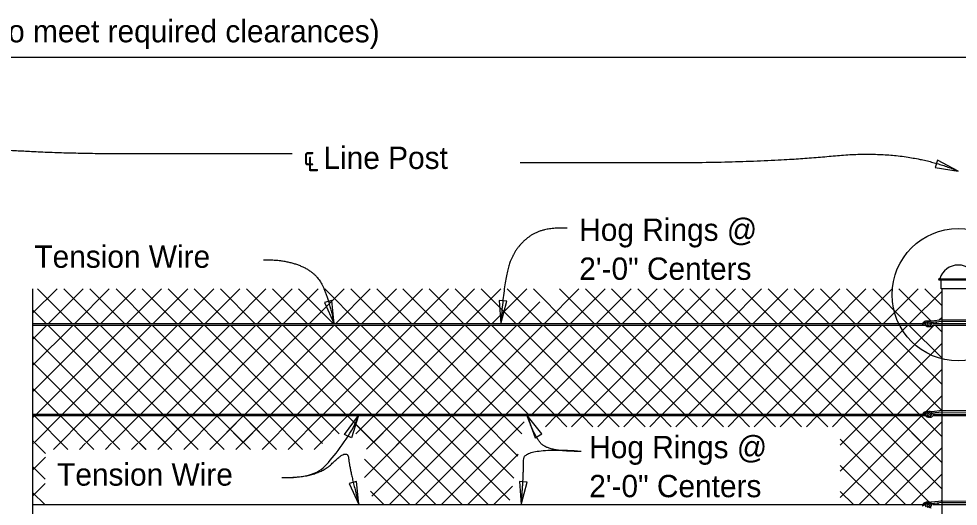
# Model space of a CAD drawing. Extents: x 0 to 41, y -96 to 25.
# Drawn here: x 16.84 to 25.32, y 20.56 to 24.96 of the extents above; entities that cross this region are included whole.
import ezdxf

# ---------------------------------------------------------------- set-up
doc = ezdxf.new("R2010")
doc.units = 0
for name, color, linetype in [('Dimension', 7, 'Continuous'), ('Miscellaneous', 7, 'Continuous'), ('SteelMisc', 7, 'Continuous'), ('SteelMisc_h', 7, 'Continuous'), ('TextStructures', 7, 'Continuous')]:
    doc.layers.add(name, color=color, linetype=linetype)

msp = doc.modelspace()

# ---------------------------------------------------------------- linework, layer by layer
at = {"layer": 'Dimension'}
for points in [[(14.3237, 24.6092), (15.7874, 24.6092), (15.7874, 24.7126), (15.8324, 24.6092), (15.8774, 24.5059), (15.8774, 24.6092), (29.1682, 24.6092)], [(16.9607, 22.5181), (16.9607, 19.3509), (17.064, 19.3509), (16.9607, 19.3059), (16.8574, 19.2609), (16.9607, 19.2609), (16.9607, 18.3673)]]:
    msp.add_lwpolyline(points, dxfattribs=at)
for points in [[(25.3238, 23.582), (25.1374, 23.6813), (25.1151, 23.6144)], [(19.6851, 22.2037), (19.6649, 22.414), (19.5967, 22.3956)], [(21.1903, 22.2037), (21.2464, 22.4074), (21.1762, 22.4145)], [(19.9044, 21.3734), (19.8413, 21.1718), (19.7784, 21.2039)], [(21.4293, 21.3734), (21.5009, 21.1747), (21.5624, 21.2094)], [(19.9087, 20.57), (19.8885, 20.7803), (19.8203, 20.7619)], [(21.3736, 20.5698), (21.4296, 20.7734), (21.3594, 20.7805)]]:
    msp.add_lwpolyline(points, close=True, dxfattribs=at)
msp.add_circle((25.3237, 22.4656), 0.5976, dxfattribs=at)
for points, degree in [([(19.3053, 23.7363), (18.502, 23.7363), (17.1126, 23.7363), (15.9312, 23.8309), (15.3237, 23.935)], 2), ([(21.3649, 23.6582), (21.8115, 23.6582), (23.579, 23.6582), (24.8456, 23.7812), (25.3237, 23.5819)], 2), ([(21.79, 23.0656), (21.5721, 23.0781), (21.3283, 22.9036), (21.2222, 22.6197), (21.1904, 22.2037)], 2), ([(19.0466, 22.7791), (19.227, 22.7862), (19.51, 22.6764), (19.6303, 22.4569), (19.6851, 22.2037)], 2), ([(19.2125, 20.8146), (19.5006, 20.8172), (19.62, 20.9127), (19.8603, 21.2414), (19.904, 21.3726)], 3), ([(21.9165, 21.0507), (21.6205, 21.0483), (21.4904, 21.1931), (21.4293, 21.3734)], 2), ([(21.9165, 21.0507), (21.3904, 21.0866), (21.3958, 20.8597), (21.3736, 20.5697)], 2), ([(19.2125, 20.8146), (19.5352, 20.808), (19.8072, 21.083), (19.8238, 20.8929), (19.9086, 20.57)], 2)]:
    msp.add_open_spline(points, degree=degree, dxfattribs=at)
at = {"layer": 'Miscellaneous'}
for p, q in [((16.9607, 22.2978), (17.181, 22.5181)), ((17.0061, 22.5181), (17.3187, 22.2055)), ((17.1046, 22.2055), (17.4171, 22.5181)), ((17.2423, 22.5181), (17.5548, 22.2055)), ((17.3408, 22.2055), (17.6533, 22.5181)), ((17.4785, 22.5181), (17.791, 22.2055)), ((17.577, 22.2055), (17.8895, 22.5181)), ((17.7142, 22.5181), (18.0267, 22.2055)), ((17.8131, 22.2055), (18.1257, 22.5181)), ((17.9499, 22.5181), (18.2624, 22.2055)), ((18.0493, 22.2055), (18.3618, 22.5181)), ((18.1856, 22.5181), (18.4981, 22.2055)), ((18.285, 22.2055), (18.5975, 22.5181)), ((18.4213, 22.5181), (18.7338, 22.2055)), ((18.5207, 22.2055), (18.8332, 22.5181)), ((18.657, 22.5181), (18.9695, 22.2055)), ((18.7564, 22.2055), (19.0689, 22.5181)), ((18.8927, 22.5181), (19.2052, 22.2055)), ((18.9921, 22.2055), (19.3047, 22.5181)), ((19.1284, 22.5181), (19.4409, 22.2055)), ((19.2278, 22.2055), (19.5404, 22.5181)), ((19.3641, 22.5181), (19.6766, 22.2055)), ((19.4635, 22.2055), (19.7761, 22.5181)), ((19.5998, 22.5181), (19.9123, 22.2055)), ((19.6992, 22.2055), (20.0118, 22.5181)), ((19.8355, 22.5181), (20.148, 22.2055)), ((19.9349, 22.2055), (20.2475, 22.5181)), ((20.0712, 22.5181), (20.3837, 22.2055)), ((20.1706, 22.2055), (20.4832, 22.5181)), ((20.3069, 22.5181), (20.6194, 22.2055)), ((20.4063, 22.2055), (20.7189, 22.5181)), ((20.5426, 22.5181), (20.8551, 22.2055)), ((20.642, 22.2055), (20.9546, 22.5181)), ((20.7783, 22.5181), (21.0908, 22.2055)), ((20.8777, 22.2055), (21.1903, 22.5181)), ((21.014, 22.5181), (21.3265, 22.2055)), ((21.1134, 22.2055), (21.426, 22.5181)), ((21.2497, 22.5181), (21.5622, 22.2055)), ((21.4854, 22.5181), (21.7979, 22.2055)), ((21.5848, 22.2055), (21.8974, 22.5181)), ((21.7211, 22.5181), (22.0336, 22.2055)), ((21.8205, 22.2055), (22.1331, 22.5181)), ((21.9568, 22.5181), (22.2693, 22.2055)), ((22.0562, 22.2055), (22.3688, 22.5181)), ((22.1925, 22.5181), (22.505, 22.2055)), ((22.2919, 22.2055), (22.6045, 22.5181)), ((22.4282, 22.5181), (22.7407, 22.2055)), ((22.5276, 22.2055), (22.8402, 22.5181)), ((22.6639, 22.5181), (22.9765, 22.2055)), ((22.7634, 22.2055), (23.0759, 22.5181)), ((22.8996, 22.5181), (23.2122, 22.2055)), ((22.9991, 22.2055), (23.3116, 22.5181)), ((23.1353, 22.5181), (23.4479, 22.2055)), ((23.2348, 22.2055), (23.5473, 22.5181)), ((23.371, 22.5181), (23.6836, 22.2055)), ((23.4705, 22.2055), (23.783, 22.5181)), ((23.6067, 22.5181), (23.9193, 22.2055)), ((23.7062, 22.2055), (24.0187, 22.5181)), ((23.8424, 22.5181), (24.155, 22.2055)), ((23.9419, 22.2055), (24.2544, 22.5181)), ((24.0786, 22.5181), (24.3911, 22.2055)), ((24.1776, 22.2055), (24.4901, 22.5181)), ((24.3148, 22.5181), (24.6273, 22.2055)), ((24.4133, 22.2055), (24.7258, 22.5181)), ((24.5509, 22.5181), (24.8635, 22.2055)), ((24.649, 22.2055), (24.9615, 22.5181)), ((24.7871, 22.5181), (25.0782, 22.227)), ((24.8847, 22.2055), (25.1779, 22.4988)), ((25.0233, 22.5181), (25.1779, 22.3635)), ((16.9607, 22.3273), (17.0825, 22.2055)), ((21.3496, 22.2055), (21.5441, 22.4)), ((25.1494, 22.2346), (25.1779, 22.2631)), ((16.9607, 21.5893), (17.5622, 22.1908)), ((16.9607, 21.8254), (17.326, 22.1908)), ((16.9607, 22.0616), (17.0899, 22.1908)), ((16.9957, 21.3881), (17.7984, 22.1908)), ((17.0972, 22.1908), (17.8999, 21.3881)), ((17.2319, 21.3881), (18.0346, 22.1908)), ((17.3334, 22.1908), (18.1361, 21.3881)), ((17.4676, 21.3881), (18.2703, 22.1908)), ((17.5696, 22.1908), (18.3722, 21.3881)), ((17.7033, 21.3881), (18.506, 22.1908)), ((17.8058, 22.1908), (18.6084, 21.3881)), ((17.939, 21.3881), (18.7417, 22.1908)), ((18.0415, 22.1908), (18.8441, 21.3881)), ((18.1747, 21.3881), (18.9774, 22.1908)), ((18.2772, 22.1908), (19.0798, 21.3881)), ((18.4104, 21.3881), (19.2131, 22.1908)), ((18.5129, 22.1908), (19.3155, 21.3881)), ((18.6461, 21.3881), (19.4488, 22.1908)), ((18.7486, 22.1908), (19.5512, 21.3881)), ((18.8818, 21.3881), (19.6845, 22.1908)), ((18.9843, 22.1908), (19.7869, 21.3881)), ((19.1175, 21.3881), (19.9202, 22.1908)), ((19.22, 22.1908), (20.0226, 21.3881)), ((19.3532, 21.3881), (20.1559, 22.1908)), ((19.4557, 22.1908), (20.2583, 21.3881)), ((19.5889, 21.3881), (20.3916, 22.1908)), ((19.6914, 22.1908), (20.494, 21.3881)), ((19.8246, 21.3881), (20.6273, 22.1908)), ((19.9271, 22.1908), (20.7297, 21.3881)), ((20.0603, 21.3881), (20.863, 22.1908)), ((20.1628, 22.1908), (20.9654, 21.3881)), ((20.296, 21.3881), (21.0987, 22.1908)), ((20.3985, 22.1908), (21.2011, 21.3881)), ((20.5322, 21.3881), (21.3349, 22.1908)), ((20.6342, 22.1908), (21.4368, 21.3881)), ((20.7674, 21.3881), (21.5701, 22.1908)), ((20.8699, 22.1908), (21.6725, 21.3881)), ((21.0031, 21.3881), (21.8058, 22.1908)), ((21.1056, 22.1908), (21.9082, 21.3881)), ((21.2388, 21.3881), (22.0415, 22.1908)), ((21.3413, 22.1908), (22.1439, 21.3881)), ((21.4745, 21.3881), (22.2772, 22.1908)), ((21.577, 22.1908), (22.3796, 21.3881)), ((21.7103, 21.3881), (22.5129, 22.1908)), ((21.8127, 22.1908), (22.6153, 21.3881)), ((21.946, 21.3881), (22.7486, 22.1908)), ((22.0484, 22.1908), (22.851, 21.3881)), ((22.1817, 21.3881), (22.9843, 22.1908)), ((22.2841, 22.1908), (23.0867, 21.3881)), ((22.4174, 21.3881), (23.22, 22.1908)), ((22.5198, 22.1908), (23.3224, 21.3881)), ((22.6531, 21.3881), (23.4557, 22.1908)), ((22.7555, 22.1908), (23.5581, 21.3881)), ((22.8888, 21.3881), (23.6914, 22.1908)), ((22.9912, 22.1908), (23.7938, 21.3881)), ((23.1245, 21.3881), (23.9271, 22.1908)), ((23.2269, 22.1908), (24.0296, 21.3881)), ((23.3602, 21.3881), (24.1628, 22.1908)), ((23.4626, 22.1908), (24.2653, 21.3881)), ((23.5959, 21.3881), (24.3985, 22.1908)), ((23.6983, 22.1908), (24.501, 21.3881)), ((23.8316, 21.3881), (24.6342, 22.1908)), ((23.934, 22.1908), (24.7367, 21.3881)), ((24.0673, 21.3881), (24.8699, 22.1908)), ((24.1697, 22.1908), (24.9724, 21.3881)), ((24.303, 21.3881), (25.1056, 22.1908)), ((24.4059, 22.1908), (25.1762, 21.4205)), ((24.6421, 22.1908), (25.1779, 21.6549)), ((24.8782, 22.1908), (25.1779, 21.8911)), ((25.0931, 22.2121), (25.0997, 22.2055)), ((25.1144, 22.1908), (25.1779, 22.1273)), ((25.1204, 22.2055), (25.1339, 22.2191)), ((16.9607, 22.0911), (17.6637, 21.3881)), ((24.5387, 21.3881), (25.1779, 22.0274)), ((16.9607, 21.8573), (17.4299, 21.3881)), ((24.7744, 21.3881), (25.1779, 21.7917)), ((16.9607, 21.6216), (17.1942, 21.3881)), ((25.0311, 21.4092), (25.1779, 21.556)), ((16.9607, 21.3531), (16.981, 21.3734)), ((16.9732, 21.3734), (17.2782, 21.0685)), ((16.9823, 21.1385), (17.2172, 21.3734)), ((17.1479, 21.0685), (17.4529, 21.3734)), ((17.2089, 21.3734), (17.5139, 21.0685)), ((17.4446, 21.3734), (17.7496, 21.0685)), ((17.4537, 21.1385), (17.6886, 21.3734)), ((17.6785, 21.3734), (17.9834, 21.0685)), ((17.6894, 21.1385), (17.9243, 21.3734)), ((17.9146, 21.3734), (18.2196, 21.0685)), ((17.9251, 21.1385), (18.16, 21.3734)), ((17.9843, 21.3051), (18.1509, 21.1385)), ((18.0907, 21.0685), (18.3957, 21.3734)), ((18.1508, 21.3734), (18.4557, 21.0685)), ((18.1608, 21.1385), (18.3274, 21.3051)), ((18.22, 21.3051), (18.3867, 21.1385)), ((18.3264, 21.0685), (18.6314, 21.3734)), ((18.387, 21.3734), (18.6919, 21.0685)), ((18.3965, 21.1385), (18.5631, 21.3051)), ((18.4557, 21.3051), (18.6224, 21.1385)), ((18.5622, 21.0685), (18.8671, 21.3734)), ((18.6231, 21.3734), (18.9281, 21.0685)), ((18.6322, 21.1385), (18.7988, 21.3051)), ((18.6914, 21.3051), (18.8581, 21.1385)), ((18.7979, 21.0685), (19.1028, 21.3734)), ((18.8589, 21.3734), (19.1638, 21.0685)), ((18.8679, 21.1385), (19.0345, 21.3051)), ((18.9271, 21.3051), (19.0938, 21.1385)), ((19.0336, 21.0685), (19.3385, 21.3734)), ((19.0946, 21.3734), (19.3995, 21.0685)), ((19.1036, 21.1385), (19.2702, 21.3051)), ((19.1628, 21.3051), (19.3295, 21.1385)), ((19.2693, 21.0685), (19.5742, 21.3734)), ((19.3303, 21.3734), (19.5808, 21.1228)), ((19.3393, 21.1385), (19.5059, 21.3051)), ((19.3985, 21.3051), (19.5652, 21.1385)), ((19.505, 21.0685), (19.8099, 21.3734)), ((19.566, 21.3734), (19.7305, 21.2089)), ((19.8017, 21.3734), (20.6051, 20.57)), ((19.8699, 21.3051), (20.0366, 21.1385)), ((19.8814, 21.2092), (19.9773, 21.3051)), ((19.8849, 21.2127), (20.0456, 21.3734)), ((19.9699, 20.8258), (20.5175, 21.3734)), ((19.9787, 21.0709), (20.2813, 21.3734)), ((20.0266, 20.6473), (20.7527, 21.3734)), ((20.0374, 21.3734), (20.2772, 21.1336)), ((20.0464, 21.1385), (20.213, 21.3051)), ((20.2731, 21.3734), (20.5129, 21.1336)), ((20.5088, 21.3734), (20.7486, 21.1336)), ((20.6564, 20.57), (21.4026, 21.3162)), ((20.7445, 21.3734), (20.9843, 21.1336)), ((20.7486, 21.1336), (20.9884, 21.3734)), ((20.9802, 21.3734), (21.3445, 21.009)), ((20.9843, 21.1336), (21.2241, 21.3734)), ((21.2159, 21.3734), (21.3808, 21.2085)), ((21.5949, 21.2728), (21.6955, 21.3734)), ((21.6873, 21.3734), (21.7879, 21.2728)), ((21.8306, 21.2728), (21.9312, 21.3734)), ((21.923, 21.3734), (22.0236, 21.2728)), ((22.0663, 21.2728), (22.1669, 21.3734)), ((22.1587, 21.3734), (22.2593, 21.2728)), ((22.302, 21.2728), (22.4026, 21.3734)), ((22.3944, 21.3734), (22.495, 21.2728)), ((22.5377, 21.2728), (22.6383, 21.3734)), ((22.6301, 21.3734), (22.7307, 21.2728)), ((22.7734, 21.2728), (22.874, 21.3734)), ((22.8658, 21.3734), (22.9664, 21.2728)), ((23.0091, 21.2728), (23.1097, 21.3734)), ((23.1015, 21.3734), (23.2021, 21.2728)), ((23.2448, 21.2728), (23.3454, 21.3734)), ((23.3372, 21.3734), (23.4378, 21.2728)), ((23.4805, 21.2728), (23.5811, 21.3734)), ((23.5729, 21.3734), (23.6735, 21.2728)), ((23.7162, 21.2728), (23.8168, 21.3734)), ((23.8086, 21.3734), (23.9092, 21.2728)), ((23.9519, 21.2728), (24.0525, 21.3734)), ((24.0443, 21.3734), (24.1449, 21.2728)), ((24.1876, 21.2728), (24.2882, 21.3734)), ((24.28, 21.3734), (24.5198, 21.1336)), ((24.2841, 21.1336), (24.5239, 21.3734)), ((24.4276, 20.57), (25.1779, 21.3203)), ((24.5157, 21.3734), (24.7555, 21.1336)), ((24.5198, 21.1336), (24.7596, 21.3734)), ((24.7514, 21.3734), (25.1779, 20.9469)), ((24.7555, 21.1336), (24.9953, 21.3734)), ((24.8196, 21.3051), (24.9863, 21.1385)), ((24.9871, 21.3734), (25.1779, 21.1826)), ((24.9961, 21.1385), (25.1628, 21.3051)), ((16.9607, 21.1498), (17.0781, 21.0324)), ((19.575, 21.1385), (19.59, 21.1535)), ((24.2578, 21.1599), (24.8477, 20.57)), ((16.9607, 21.1169), (16.9675, 21.1237)), ((17.3836, 21.0685), (17.4389, 21.1237)), ((17.6193, 21.0685), (17.6746, 21.1237)), ((17.855, 21.0685), (17.9103, 21.1237)), ((17.93, 21.1237), (17.9853, 21.0685)), ((19.9585, 20.8149), (20.2772, 21.1336)), ((20.185, 20.57), (20.7486, 21.1336)), ((20.2774, 21.1333), (20.8408, 20.57)), ((20.4207, 20.57), (20.9843, 21.1336)), ((20.5129, 21.1336), (21.0765, 20.57)), ((20.7486, 21.1336), (21.272, 20.6101)), ((20.9843, 21.1336), (21.3083, 20.8096)), ((24.2578, 21.1073), (24.2841, 21.1336)), ((24.2578, 20.8716), (24.5198, 21.1336)), ((24.2578, 20.6359), (24.7555, 21.1336)), ((24.5198, 21.1336), (25.0612, 20.5922)), ((24.6633, 20.57), (25.1779, 21.0846)), ((24.7555, 21.1336), (25.1779, 20.7112)), ((16.9607, 20.8812), (17.0776, 20.9982)), ((19.9588, 20.9806), (20.3694, 20.57)), ((20.8921, 20.57), (21.3475, 21.0254)), ((16.9607, 20.9145), (17.0752, 20.8)), ((24.2578, 20.9242), (24.612, 20.57)), ((24.899, 20.57), (25.1779, 20.8489)), ((16.9607, 20.6455), (17.0747, 20.7596)), ((21.1278, 20.57), (21.2951, 20.7373)), ((16.9607, 20.6788), (17.0696, 20.57)), ((20.0127, 20.6909), (20.1337, 20.57)), ((24.2578, 20.6885), (24.3763, 20.57)), ((25.1347, 20.57), (25.1499, 20.5852)), ((25.1659, 20.6012), (25.1779, 20.6132))]:
    msp.add_line(p, q, dxfattribs=at)
at = {"layer": 'SteelMisc'}
for p, q in [((25.1514, 22.6101), (25.496, 22.6101)), ((25.496, 22.5978), (25.1514, 22.5978)), ((25.1697, 22.5181), (25.1697, 22.5978)), ((25.4778, 22.5181), (25.1697, 22.5181)), ((25.1779, 14.97), (25.1779, 22.5181)), ((25.1779, 22.2381), (25.4691, 22.2398)), ((16.9607, 22.2055), (25.0028, 22.2055)), ((16.9607, 22.1908), (25.0294, 22.1908)), ((25.0127, 22.2055), (25.0259, 22.2055)), ((25.1779, 22.2381), (25.0851, 22.2265)), ((25.1779, 22.2236), (25.0851, 22.214)), ((25.0943, 22.1908), (25.1779, 22.1908)), ((25.0958, 22.2055), (25.1779, 22.2055)), ((25.1779, 22.2236), (25.4691, 22.2253)), ((25.1779, 21.4207), (25.0851, 21.4091)), ((25.1779, 21.4062), (25.0851, 21.3966)), ((25.1779, 21.4207), (25.4691, 21.4224)), ((25.1779, 21.4062), (25.4691, 21.4079)), ((16.9607, 21.3881), (25.0028, 21.3881)), ((16.9607, 21.3734), (25.0294, 21.3734)), ((25.0127, 21.3881), (25.0259, 21.3881)), ((25.0943, 21.3734), (25.1779, 21.3734)), ((25.0958, 21.3881), (25.1779, 21.3881)), ((16.9607, 20.57), (25.0028, 20.57)), ((25.0127, 20.57), (25.0259, 20.57)), ((25.1779, 20.6026), (25.0792, 20.591)), ((25.1779, 20.5881), (25.0853, 20.5785)), ((25.0958, 20.57), (25.1779, 20.57)), ((25.1779, 20.6026), (25.4691, 20.6043)), ((25.1779, 20.5881), (25.4691, 20.5897))]:
    msp.add_line(p, q, dxfattribs=at)
msp.add_arc((25.1516, 22.6038), 0.00613, 91.1647, 268.8353, dxfattribs=at)
for centre, major_axis, ratio, start_param, end_param in [((25.3244, 22.569), (0.1711, 0), 0.957868, 0.252602, 2.888574), ((25.037, 22.1913), (0.0373, 0), 0.957868, 1.427863, 3.108042), ((25.0581, 22.1516), (-0.0724, 0), 0.957868, 5.133134, 5.652106), ((25.0507, 22.2032), (-0.0249, 0), 0.957868, 5.913851, 7.104804), ((25.0495, 22.2057), (0.023, 0), 0.957868, 1.234085, 2.861055), ((25.052, 22.1992), (0.0231, 0), 0.957868, 3.795406, 4.839145), ((25.0683, 22.2004), (0.0295, 0), 0.957868, 1.132635, 3.996184), ((25.0581, 22.1935), (0.0206, -0.0021), 0.798607, 4.32653, 5.170153), ((25.0817, 22.2022), (-0.0303, -0.0108), 0.724765, 4.35367, 6.224248), ((25.0716, 22.1935), (0.0206, -0.0021), 0.798607, 3.319436, 5.220153), ((25.0784, 22.1981), (-0.0139, 0), 0.957868, 5.075258, 6.485782), ((25.0728, 22.1957), (-0.00795, 0), 0.957868, 0.039428, 2.999692), ((25.0868, 22.1892), (-0.0259, 0), 0.957868, 4.777514, 5.251802), ((25.0711, 22.2015), (0.0119, 0), 0.957868, 5.725876, 7.416677), ((25.0642, 22.2123), (0.0391, 0), 0.957868, 5.134108, 5.414681), ((25.0711, 22.2015), (0.0119, 0), 0.957868, 5.639684, 5.723117), ((25.0713, 22.2003), (0.0251, 0), 0.957868, 5.523427, 5.877802), ((25.0713, 22.2003), (0.0251, 0), 0.957868, 0.221743, 0.642584), ((25.037, 21.3739), (0.0373, 0), 0.957868, 1.427863, 3.108042), ((25.0581, 21.3342), (-0.0724, 0), 0.957868, 5.133134, 5.652106), ((25.0507, 21.3858), (-0.0249, 0), 0.957868, 5.913851, 7.089857), ((25.0495, 21.3883), (0.023, 0), 0.957868, 1.234085, 2.861055), ((25.0683, 21.383), (0.0295, 0), 0.957868, 1.132635, 3.996184), ((25.0817, 21.3848), (-0.0303, -0.0108), 0.724765, 4.35367, 6.224248), ((25.0784, 21.3807), (-0.0139, 0), 0.957868, 5.075258, 6.485782), ((25.0868, 21.3718), (-0.0259, 0), 0.957868, 4.777514, 5.251802), ((25.0711, 21.3841), (0.0119, 0), 0.957868, 5.725876, 7.416677), ((25.0713, 21.3829), (0.0251, 0), 0.957868, 0.221743, 0.642584), ((25.052, 21.3818), (0.0231, 0), 0.957868, 3.779554, 4.839145), ((25.0581, 21.3761), (0.0206, -0.0021), 0.798607, 4.32653, 5.170153), ((25.0716, 21.3761), (0.0206, -0.0021), 0.798607, 3.319436, 5.220153), ((25.0728, 21.3783), (-0.00795, 0), 0.957868, 0.039428, 2.999692), ((25.0642, 21.3949), (0.0391, 0), 0.957868, 5.134108, 5.41974), ((25.0711, 21.3841), (0.0119, 0), 0.957868, 5.639684, 5.723117), ((25.0713, 21.3829), (0.0251, 0), 0.957868, 5.531357, 5.877802), ((25.037, 20.5557), (0.0373, 0), 0.957868, 1.427863, 3.108042), ((25.0581, 20.516), (-0.0724, 0), 0.957868, 5.133134, 5.652106), ((25.0507, 20.5677), (-0.0249, 0), 0.957868, 6.009018, 7.089857), ((25.0495, 20.5702), (0.023, 0), 0.957868, 1.234085, 2.970541), ((25.0683, 20.5648), (0.0295, 0), 0.957868, 1.132635, 3.996184), ((25.0817, 20.5666), (-0.0303, -0.0108), 0.724765, 4.490702, 7.536078), ((25.0784, 20.5625), (-0.0139, 0), 0.957868, 5.822914, 6.485782), ((25.0728, 20.5601), (-0.00795, 0), 0.957868, 0.039428, 2.999692), ((25.0868, 20.5537), (-0.0259, 0), 0.957868, 4.502074, 5.646371), ((25.0711, 20.5659), (0.0119, 0), 0.957868, 5.725876, 7.416677), ((25.0711, 20.5659), (0.0119, 0), 0.957868, 5.639684, 5.723117), ((25.0713, 20.5647), (0.0251, 0), 0.957868, 0.221743, 0.584336)]:
    msp.add_ellipse(centre, major_axis=major_axis, ratio=ratio, start_param=start_param, end_param=end_param, dxfattribs=at)
at = {"layer": 'SteelMisc_h'}
for p, q in [((25.1779, 22.2055), (25.4696, 22.2055)), ((25.1779, 22.1908), (25.4696, 22.1908)), ((25.1779, 21.3881), (25.4696, 21.3881)), ((25.1779, 21.3734), (25.4696, 21.3734)), ((25.1779, 20.57), (25.4696, 20.57))]:
    msp.add_line(p, q, dxfattribs=at)

# ---------------------------------------------------------------- texts
at = {"layer": 'Dimension'}
for s, p in [('Hog Rings @ ', (21.8998, 22.9514)), ('2\'-0" Centers', (21.8998, 22.5994)), ('Hog Rings @ ', (21.9899, 20.9891)), ('2\'-0" Centers', (21.9899, 20.6371))]:
    msp.add_text(s, height=0.2016, dxfattribs=at).set_placement(p)
at = {"layer": 'TextStructures'}
for s, p in [('Equal Spaces @ 10\'-0" Max. (Posts may be shifted minimally to meet required clearances)', (9.2913, 24.7438)), ('℄ Line Post', (19.4045, 23.6006)), ('Tension Wire', (16.9767, 22.7086)), ('Tension Wire', (17.1819, 20.7415))]:
    msp.add_text(s, height=0.2016, dxfattribs=at).set_placement(p)

doc.saveas('drawing.dxf')
